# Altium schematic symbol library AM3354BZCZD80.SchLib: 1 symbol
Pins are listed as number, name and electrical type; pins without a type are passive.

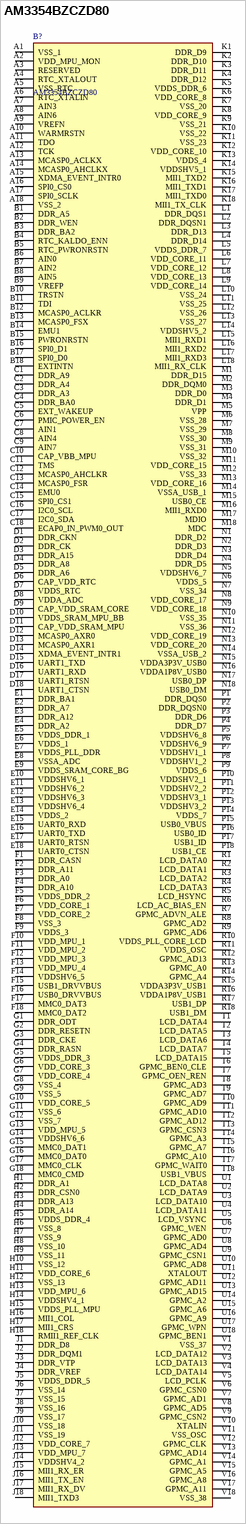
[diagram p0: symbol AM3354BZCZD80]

## AM3354BZCZD80
designator B?
<p>Sitara processor: Arm Cortex-A8, 3D graphics, CAN</p>; Manufacturer_Name: Texas Instruments; Geometry.Height: 1.4mm
footprint BGA324C80P18X18_1500X1500X140
pins: A1 VSS_1, A2 VDD_MPU_MON, A3 RESERVED, A4 RTC_XTALOUT, A5 VSS_RTC, A6 RTC_XTALIN, A7 AIN3, A8 AIN6, A9 VREFN, A10 WARMRSTN, A11 TDO, A12 TCK, A13 MCASP0_ACLKX, A14 MCASP0_AHCLKX, A15 XDMA_EVENT_INTR0, A16 SPI0_CS0, A17 SPI0_SCLK, A18 VSS_2, B1 DDR_A5, B2 DDR_WEN, B3 DDR_BA2, B4 RTC_KALDO_ENN, B5 RTC_PWRONRSTN, B6 AIN0, B7 AIN2, B8 AIN5, B9 VREFP, B10 TRSTN, B11 TDI, B12 MCASP0_ACLKR, B13 MCASP0_FSX, B14 EMU1, B15 PWRONRSTN, B16 SPI0_D1, B17 SPI0_D0, B18 EXTINTN, C1 DDR_A9, C2 DDR_A4, C3 DDR_A3, C4 DDR_BA0, C5 EXT_WAKEUP, C6 PMIC_POWER_EN, C7 AIN1, C8 AIN4, C9 AIN7, C10 CAP_VBB_MPU, C11 TMS, C12 MCASP0_AHCLKR, C13 MCASP0_FSR, C14 EMU0, C15 SPI0_CS1, C16 I2C0_SCL, C17 I2C0_SDA, C18 ECAP0_IN_PWM0_OUT, D1 DDR_CKN, D2 DDR_CK, D3 DDR_A15, D4 DDR_A8, D5 DDR_A6, D6 CAP_VDD_RTC, D7 VDDS_RTC, D8 VDDA_ADC, D9 CAP_VDD_SRAM_CORE, D10 VDDS_SRAM_MPU_BB, D11 CAP_VDD_SRAM_MPU, D12 MCASP0_AXR0, D13 MCASP0_AXR1, D14 XDMA_EVENT_INTR1, D15 UART1_TXD, D16 UART1_RXD, D17 UART1_RTSN, D18 UART1_CTSN, E1 DDR_BA1, E2 DDR_A7, E3 DDR_A12, E4 DDR_A2, E5 VDDS_DDR_1, E6 VDDS_1, E7 VDDS_PLL_DDR, E8 VSSA_ADC, E9 VDDS_SRAM_CORE_BG, E10 VDDSHV6_1, E11 VDDSHV6_2, E12 VDDSHV6_3, E13 VDDSHV6_4, E14 VDDS_2, E15 UART0_RXD, E16 UART0_TXD, E17 UART0_RTSN, E18 UART0_CTSN, F1 DDR_CASN, F2 DDR_A11, F3 DDR_A0, F4 DDR_A10, F5 VDDS_DDR_2, F6 VDD_CORE_1, F7 VDD_CORE_2, F8 VSS_3, F9 VDDS_3, F10 VDD_MPU_1, F11 VDD_MPU_2, F12 VDD_MPU_3, F13 VDD_MPU_4, F14 VDDSHV6_5, F15 USB1_DRVVBUS, F16 USB0_DRVVBUS, F17 MMC0_DAT3, F18 MMC0_DAT2, G1 DDR_ODT, G2 DDR_RESETN, G3 DDR_CKE, G4 DDR_RASN, G5 VDDS_DDR_3, G6 VDD_CORE_3, G7 VDD_CORE_4, G8 VSS_4, G9 VSS_5, G10 VDD_CORE_5, G11 VSS_6, G12 VSS_7, G13 VDD_MPU_5, G14 VDDSHV6_6, G15 MMC0_DAT1, G16 MMC0_DAT0, G17 MMC0_CLK, G18 MMC0_CMD, H1 DDR_A1, H2 DDR_CSN0, H3 DDR_A13, H4 DDR_A14, H5 VDDS_DDR_4, H6 VSS_8, H7 VSS_9, H8 VSS_10, H9 VSS_11, H10 VSS_12, H11 VDD_CORE_6, H12 VSS_13, H13 VDD_MPU_6, H14 VDDSHV4_1, H15 VDDS_PLL_MPU, H16 MII1_COL, H17 MII1_CRS, H18 RMII1_REF_CLK, J1 DDR_D8, J2 DDR_DQM1, J3 DDR_VTP, J4 DDR_VREF, J5 VDDS_DDR_5, J6 VSS_14, J7 VSS_15, J8 VSS_16, J9 VSS_17, J10 VSS_18, J11 VSS_19, J12 VDD_CORE_7, J13 VDD_MPU_7, J14 VDDSHV4_2, J15 MII1_RX_ER, J16 MII1_TX_EN, J17 MII1_RX_DV, J18 MII1_TXD3, K1 DDR_D9, K2 DDR_D10, K3 DDR_D11, K4 DDR_D12, K5 VDDS_DDR_6, K6 VDD_CORE_8, K7 VSS_20, K8 VDD_CORE_9, K9 VSS_21, K10 VSS_22, K11 VSS_23, K12 VDD_CORE_10, K13 VDDS_4, K14 VDDSHV5_1, K15 MII1_TXD2, K16 MII1_TXD1, K17 MII1_TXD0, K18 MII1_TX_CLK, L1 DDR_DQS1, L2 DDR_DQSN1, L3 DDR_D13, L4 DDR_D14, L5 VDDS_DDR_7, L6 VDD_CORE_11, L7 VDD_CORE_12, L8 VDD_CORE_13, L9 VDD_CORE_14, L10 VSS_24, L11 VSS_25, L12 VSS_26, L13 VSS_27, L14 VDDSHV5_2, L15 MII1_RXD1, L16 MII1_RXD2, L17 MII1_RXD3, L18 MII1_RX_CLK, M1 DDR_D15, M2 DDR_DQM0, M3 DDR_D0, M4 DDR_D1, M5 VPP, M6 VSS_28, M7 VSS_29, M8 VSS_30, M9 VSS_31, M10 VSS_32, M11 VDD_CORE_15, M12 VSS_33, M13 VDD_CORE_16, M14 VSSA_USB_1, M15 USB0_CE, M16 MII1_RXD0, M17 MDIO, M18 MDC, N1 DDR_D2, N2 DDR_D3, N3 DDR_D4, N4 DDR_D5, N5 VDDSHV6_7, N6 VDDS_5, N7 VSS_34, N8 VDD_CORE_17, N9 VDD_CORE_18, N10 VSS_35, N11 VSS_36, N12 VDD_CORE_19, N13 VDD_CORE_20, N14 VSSA_USB_2, N15 VDDA3P3V_USB0, N16 VDDA1P8V_USB0, N17 USB0_DP, N18 USB0_DM, P1 DDR_DQS0, P2 DDR_DQSN0, P3 DDR_D6, P4 DDR_D7, P5 VDDSHV6_8, P6 VDDSHV6_9, P7 VDDSHV1_1, P8 VDDSHV1_2, P9 VDDS_6, P10 VDDSHV2_1, P11 VDDSHV2_2, P12 VDDSHV3_1, P13 VDDSHV3_2, P14 VDDS_7, P15 USB0_VBUS, P16 USB0_ID, P17 USB1_ID, P18 USB1_CE, R1 LCD_DATA0, R2 LCD_DATA1, R3 LCD_DATA2, R4 LCD_DATA3, R5 LCD_HSYNC, R6 LCD_AC_BIAS_EN, R7 GPMC_ADVN_ALE, R8 GPMC_AD2, R9 GPMC_AD6, R10 VDDS_PLL_CORE_LCD, R11 VDDS_OSC, R12 GPMC_AD13, R13 GPMC_A0, R14 GPMC_A4, R15 VDDA3P3V_USB1, R16 VDDA1P8V_USB1, R17 USB1_DP, R18 USB1_DM, T1 LCD_DATA4, T2 LCD_DATA5, T3 LCD_DATA6, T4 LCD_DATA7, T5 LCD_DATA15, T6 GPMC_BEN0_CLE, T7 GPMC_OEN_REN, T8 GPMC_AD3, T9 GPMC_AD7, T10 GPMC_AD9, T11 GPMC_AD10, T12 GPMC_AD12, T13 GPMC_CSN3, T14 GPMC_A3, T15 GPMC_A7, T16 GPMC_A10, T17 GPMC_WAIT0, T18 USB1_VBUS, U1 LCD_DATA8, U2 LCD_DATA9, U3 LCD_DATA10, U4 LCD_DATA11, U5 LCD_VSYNC, U6 GPMC_WEN, U7 GPMC_AD0, U8 GPMC_AD4, U9 GPMC_CSN1, U10 GPMC_AD8, U11 XTALOUT, U12 GPMC_AD11, U13 GPMC_AD15, U14 GPMC_A2, U15 GPMC_A6, U16 GPMC_A9, U17 GPMC_WPN, U18 GPMC_BEN1, V1 VSS_37, V2 LCD_DATA12, V3 LCD_DATA13, V4 LCD_DATA14, V5 LCD_PCLK, V6 GPMC_CSN0, V7 GPMC_AD1, V8 GPMC_AD5, V9 GPMC_CSN2, V10 XTALIN, V11 VSS_OSC, V12 GPMC_CLK, V13 GPMC_AD14, V14 GPMC_A1, V15 GPMC_A5, V16 GPMC_A8, V17 GPMC_A11, V18 VSS_38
